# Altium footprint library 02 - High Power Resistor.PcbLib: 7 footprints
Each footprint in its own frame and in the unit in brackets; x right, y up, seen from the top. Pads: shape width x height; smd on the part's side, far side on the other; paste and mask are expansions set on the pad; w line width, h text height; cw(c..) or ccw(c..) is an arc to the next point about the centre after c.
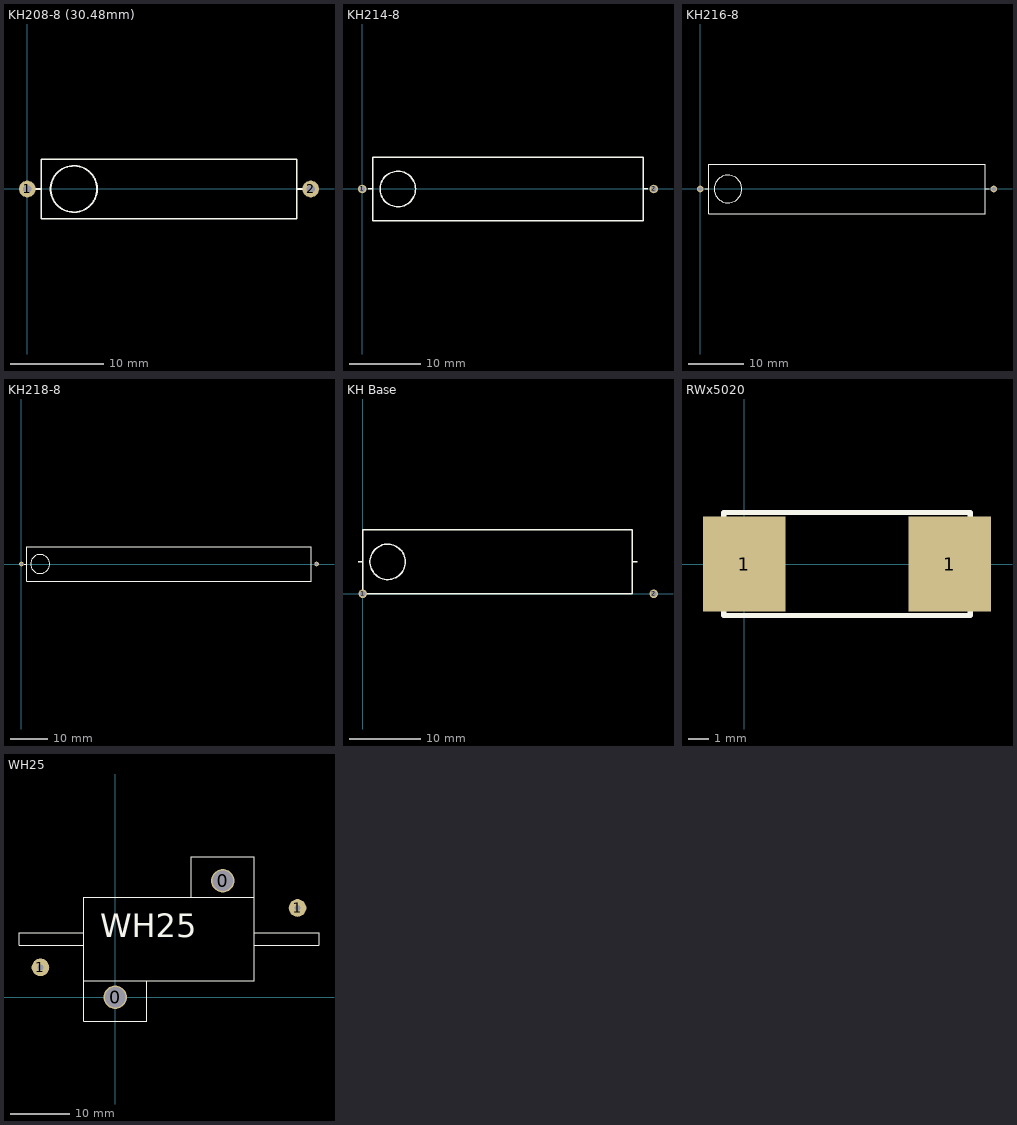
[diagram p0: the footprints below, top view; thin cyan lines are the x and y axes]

## KH208-8 (30.48mm) [mm] "Axial - 30.48mm, Body: 25mm x 6.4mm"
height 6.4
pads (2):
  round 1.8 hole 0.9: 1(0,0) 2(30.48,0)
Top Overlay:
  circle w0.2: c5,0 r2.5
  lines w0.2: 0.825,0 1.5,0 ; 28.98,-3.2 28.98,3.2 ; 28.98,0 29.655,0 ; 28.981,-3.2 1.5,-3.2 1.5,3.2 28.981,3.2
3D body: height 8.35, standoff -2.85, extent -0.4,-3.5 30.88,3.5

## KH214-8 [mm] "Axial - 41mm, Body: 38mm x 9mm"
height 9
pads (2):
  round 1.2 hole 0.8: 1(0,0) 2(41,0)
Top Overlay:
  circle w0.2: c5,0 r2.5
  lines w0.2: 0.825,0 1.5,0 ; 39.5,0 40.175,0 ; 1.5,-4.5 1.5,4.5 39.5,4.5 39.5,-4.5 1.5,-4.5

## KH216-8 [mm] "Axial - 53mm, Body: 50mm x 9mm"
height 9
pads (2):
  round 1.2 hole 0.8: 1(0,0) 2(53,0)
Top Overlay:
  circle w0.2: c5,0 r2.5
  lines w0.2: 0.825,0 1.5,0 ; 51.5,0 52.175,0 ; 1.5,-4.5 51.5,-4.5 51.5,4.5 1.5,4.5 1.5,-4.5

## KH218-8 [mm] "Axial - 78mm, Body: 78mm x 9mm"
height 9
pads (2):
  round 1.2 hole 0.8: 1(0,0) 2(78,0)
Top Overlay:
  circle w0.2: c5,0 r2.5
  lines w0.2: 0.825,0 1.5,0 ; 75,4.5 75.675,4.5 ; 1.5,-4.5 1.5,4.5 76.5,4.5 76.5,-4.5 1.5,-4.5

## KH Base [mm] "Axial - 41mm, Body: 38mm x 9mm"
height 9
pads (2):
  round 1.2 hole 0.8: 1(0,0) 2(41,0)
Top Overlay:
  circle w0.2: c3.5,4.5 r2.5
  lines w0.2: -0.675,4.5 0,4.5 ; 38,4.5 38.675,4.5 ; 0,0 38,0 38,9 0,9 0,0

## RWx5020 [mm] "SMD Power Resistor: 12mm x 5xx x 4.5mm"
height 4.5
pads (2):
  rect 4x4.6 smd: 1(0,0) 1(10,0)
Top Overlay:
  lines w0.254: -1,-2.5 -1,2.5 11,2.5 11,-2.5 -1,-2.5

## WH25 [mm]
pads (4):
  round 4 hole 3.5: 0(0,0) 0(18.3,19.8)
  round 3 hole 1: 1(-12.7,5.08) 1(31,15.177)
Top Overlay:
  lines w0.2: -5.35,8.8 -16.35,8.8 -16.35,11 -5.35,11 ; 5.35,2.8 5.35,-4.1 -5.35,-4.1 -5.35,2.8 ; 12.95,17 12.95,23.9 23.65,23.9 23.65,17 ; 23.65,8.8 34.65,8.8 34.65,11 23.65,11 ; -5.35,2.8 -5.35,17 23.65,17 ; -5.35,2.8 23.65,2.8 23.65,17
  text "WH25" at -2.54,10.16 h4
3D body: height 13.87, standoff 0, extent -15.519,-3.835 33.706,23.597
